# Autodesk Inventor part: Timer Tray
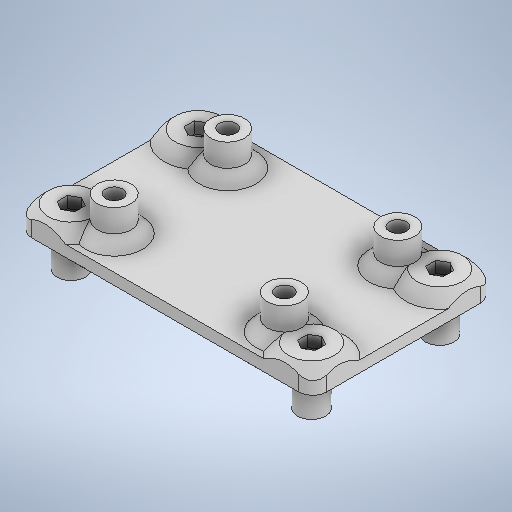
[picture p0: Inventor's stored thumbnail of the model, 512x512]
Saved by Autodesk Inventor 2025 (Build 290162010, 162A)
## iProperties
Created: 2023-12
Part Number: Timer Tray
Material: Generic
Document SubType Name: Modeling
Designer: Andrew
Density: 1 g/cm^3
Appearance: Default
Author: Andrew
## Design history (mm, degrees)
sketch "Sketch1"
  geometry: L1 (33.02, 20.32)-(-33.02, 20.32); L2 (-33.02, 20.32)-(-33.02, -20.32); L3 (-33.02, -20.32)-(33.02, -20.32); L4 (33.02, -20.32)-(33.02, 20.32); 1 further point
  constraints: 8 end point, 2 parallel, 1 horizontal, 1 perpendicular
  dimensions: "d0" = 40.64 distance of L3.end L1.start; "d1" = 66.04 distance between parallel lines of L2 L4; "d2" = 33.02 distance from line of L2 point (0, 0) (= 0.5 x d1); "d3" = 20.32 distance from line of L3 point (0, 0) (= 0.5 x d0)
extrude "Extrusion1" new body sketch "Sketch1" distance "d4" = 2.54; taper "d5" = 0 deg
fillet "Fillet1" dims "d6" = 3.175
sketch "Sketch2"
  geometry: L1 (33.02, 17.145)-(33.02, -17.145) reference; L2 (-33.02, -17.145)-(-33.02, 17.145) reference; L3 (29.845, -20.32)-(-29.845, -20.32) reference; L4 (-29.845, 20.32)-(29.845, 20.32) reference; C1 r 3.175 at (-27.051, 14.351); C2 r 1.397 at (-27.051, 14.351); C3 r 1.397 at (26.797, 14.351); C4 r 3.175 at (26.797, 14.351); C5 r 1.397 at (26.797, -14.351); C6 r 3.175 at (26.797, -14.351); C7 r 1.397 at (-27.305, -14.351); C8 r 3.175 at (-27.305, -14.351); 1 further point
  constraints: 8 centre point, 4 coincident, 2 horizontal alignment, 1 vertical alignment
  dimensions: "d7" = 2.794 diameter of C2; "d8" = 6.35 diameter of C1; "d9" = 2.794 diameter of C3 (= d7); "d10" = 6.35 diameter of C4 (= d8); "d11" = 2.794 diameter of C5 (= d7); "d12" = 6.35 diameter of C6 (= d8); "d13" = 2.794 diameter of C7 (= d7); "d14" = 6.35 diameter of C8 (= d8); "d18" = 66.04 distance between parallel lines of L1 L2 (derived); "d20" = 40.64 distance between parallel lines of L3 L4 (derived); "d42" = 56.642 dimension on C3 C2; "d43" = 31.496 dimension on C5 C3; "d44" = 28.702 distance of C5.centre C3.centre (derived); "d46" = 14.351 vertical distance of point (0, 0) C1.centre (= 0.5 x d44); "d47" = 27.051 horizontal distance of point (0, 0) C1.centre (= 0.5 x d48); "d48" = 54.102 distance of C6.centre C8.centre (derived); "d49" = 56.896 dimension on C5 C7
extrude "Extrusion2" join sketch "Sketch2" distance "d22" = 7.62; taper "d23" = 0 deg
sketch "Sketch3"
  geometry: L1 (33.02, -17.145)-(33.02, 17.145) reference; L2 (-33.02, 17.145)-(-33.02, -17.145) reference; L3 (29.845, 20.32)-(-29.845, 20.32) reference; L4 (-29.845, -20.32)-(29.845, -20.32) reference; C1 r 1.905 at (19.05, -12.7); C2 r 1.905 at (19.05, 12.7); C3 r 3.81 at (19.05, 12.7); C4 r 3.81 at (19.05, -12.7); C5 r 1.905 at (-19.05, -12.7); C6 r 3.81 at (-19.05, -12.7); C7 r 1.905 at (-19.05, 12.7); C8 r 3.81 at (-19.05, 12.7); 1 further point
  constraints: 8 centre point, 4 coincident, 2 horizontal alignment, 2 vertical alignment
  dimensions: "d24" = 3.81 diameter of C5; "d25" = 7.62 diameter of C6; "d26" = 3.81 diameter of C7 (= d24); "d27" = 7.62 diameter of C8 (= d25); "d28" = 3.81 diameter of C1 (= d24); "d29" = 7.62 diameter of C4 (= d25); "d30" = 3.81 diameter of C2 (= d26); "d31" = 7.62 diameter of C3 (= d27); "d32" = 38.1 distance of C7.centre C2.centre; "d33" = 25.4 distance of C2.centre C1.centre; "d34" = 13.97 distance from line of L1 C1.centre (= -0.5 x d32 + 0.5 x d35); "d35" = 66.04 distance between parallel lines of L2 L1 (derived); "d36" = 40.64 distance between parallel lines of L3 L4 (derived); "d37" = 7.62 distance from line of L4 C1.centre (= -0.5 x d33 + 0.5 x d36)
extrude "Extrusion3" join sketch "Sketch3" distance "d38" = 7.62; taper "d39" = 0 deg
sketch "Sketch4"
  geometry: C1 r 1.397 at (-27.051, 14.351) reference; C2 r 1.397 at (-27.305, -14.351) reference; C3 r 1.397 at (26.797, -14.351) reference; C4 r 1.397 at (26.797, 14.351) reference; C5 r 1.905 at (-19.05, 12.7) reference; C6 r 1.905 at (-19.05, -12.7) reference; C7 r 1.905 at (19.05, -12.7) reference; C8 r 1.905 at (19.05, 12.7) reference; 1 further point
extrude "Extrusion4" cut sketch "Sketch4" distance "d40" = 7.62; taper "d41" = 0 deg
sketch "Sketch5"
  geometry: L1 (-21.793, -11.116)-(-19.05, -9.532); L2 (-19.05, -9.532)-(-16.307, -11.116); L3 (-16.307, -11.116)-(-16.307, -14.284); L4 (-16.307, -14.284)-(-19.05, -15.868); L5 (-19.05, -15.868)-(-21.793, -14.284); L6 (-21.793, -14.284)-(-21.793, -11.116); L7 (-21.793, 14.284)-(-19.05, 15.868); L8 (-19.05, 15.868)-(-16.307, 14.284); L9 (-16.307, 14.284)-(-16.307, 11.116); L10 (-16.307, 11.116)-(-19.05, 9.532); L11 (-19.05, 9.532)-(-21.793, 11.116); L12 (-21.793, 11.116)-(-21.793, 14.284); L13 (16.307, -11.116)-(19.05, -9.532); L14 (19.05, -9.532)-(21.793, -11.116); L15 (21.793, -11.116)-(21.793, -14.284); L16 (21.793, -14.284)-(19.05, -15.868); L17 (19.05, -15.868)-(16.307, -14.284); L18 (16.307, -14.284)-(16.307, -11.116); L19 (16.307, 14.284)-(19.05, 15.868); L20 (19.05, 15.868)-(21.793, 14.284); L21 (21.793, 14.284)-(21.793, 11.116); L22 (21.793, 11.116)-(19.05, 9.532); L23 (19.05, 9.532)-(16.307, 11.116); L24 (16.307, 11.116)-(16.307, 14.284); C1 r 1.905 at (-19.05, -12.7) reference; C2 r 1.905 at (-19.05, 12.7) reference; C3 r 1.905 at (19.05, -12.7) reference; C4 r 1.905 at (19.05, 12.7) reference; C5 r 5.08 at (19.05, -12.7); C6 r 5.08 at (19.05, 12.7); C7 r 5.08 at (-19.05, 12.7); C8 r 5.08 at (-19.05, -12.7); 6 further points
  constraints: 48 end point, 8 coincident, 4 centre point, 4 vertical, 1 midpoint, 52 other
  dimensions: "d50" = 5.4864 distance between parallel lines of L20 L23 (= d52); "d51" = 5.4864 distance between parallel lines of L2 L5 (= d52); "d52" = 5.4864 distance between parallel lines of L10 L7; "d53" = 5.4864 distance between parallel lines of L16 L13 (= d52); "d54" = 10.16 diameter of C8; "d55" = 10.16 diameter of C7 (= d54); "d56" = 10.16 diameter of C5 (= d55); "d57" = 10.16 diameter of C6 (= d55)
extrude "Extrusion5" join sketch "Sketch5" distance "d58" = 2.54; taper "d59" = 0 deg
chamfer "Chamfer1" distance "d60" = 2.54; stored, may be unused: second distance "d61" = 3.175, angle "d62" = 45 deg
sketch "Sketch6"
  geometry: L1 (-27.305, 16.653)-(-25.311, 15.502); L2 (-25.311, 15.502)-(-25.311, 13.2); L3 (-25.311, 13.2)-(-27.305, 12.049); L4 (-27.305, 12.049)-(-29.299, 13.2); L5 (-29.299, 13.2)-(-29.299, 15.502); L6 (-29.299, 15.502)-(-27.305, 16.653); L7 (28.791, 15.502)-(28.791, 13.2); L8 (28.791, 13.2)-(26.797, 12.049); L9 (26.797, 12.049)-(24.803, 13.2); L10 (24.803, 13.2)-(24.803, 15.502); L11 (24.803, 15.502)-(26.797, 16.653); L12 (26.797, 16.653)-(28.791, 15.502); L13 (28.791, -13.2)-(28.791, -15.502); L14 (28.791, -15.502)-(26.797, -16.653); L15 (26.797, -16.653)-(24.803, -15.502); L16 (24.803, -15.502)-(24.803, -13.2); L17 (24.803, -13.2)-(26.797, -12.049); L18 (26.797, -12.049)-(28.791, -13.2); L19 (-29.045, -13.2)-(-27.051, -12.049); L20 (-27.051, -12.049)-(-25.057, -13.2); L21 (-25.057, -13.2)-(-25.057, -15.502); L22 (-25.057, -15.502)-(-27.051, -16.653); L23 (-27.051, -16.653)-(-29.045, -15.502); L24 (-29.045, -15.502)-(-29.045, -13.2); C1 r 5.08 at (26.797, 14.351); C2 r 5.08 at (26.797, -14.351); C3 r 5.08 at (-27.051, -14.351); C4 r 5.08 at (-27.305, 14.351); C5 r 1.397 at (-27.305, 14.351) reference; C6 r 1.397 at (26.797, 14.351) reference; C7 r 1.397 at (26.797, -14.351) reference; C8 r 1.397 at (-27.051, -14.351) reference; 9 further points
  constraints: 48 end point, 12 coincident, 4 centre point, 4 vertical, 52 other
  dimensions: "d63" = 3.9878 distance between parallel lines of L3 L6 (= d64); "d64" = 3.9878 distance between parallel lines of L9 L12; "d65" = 3.9878 distance between parallel lines of L14 L17 (= d64); "d66" = 3.9878 distance between parallel lines of L22 L19 (= d64); "d67" = 10.16 diameter of C4; "d68" = 10.16 diameter of C3; "d69" = 10.16 diameter of C2; "d70" = 10.16 diameter of C1
extrude "Extrusion6" join sketch "Sketch6" distance "d71" = 2.54; taper "d72" = 0 deg
chamfer "Chamfer2" distance "d73" = 2.54; stored, may be unused: second distance "d74" = 3.175, angle "d75" = 45 deg
chamfer "Chamfer3" distance "d76" = 2.54; stored, may be unused: second distance "d77" = 3.175, angle "d78" = 45 deg
body "Solid1"
node "Projected Loop1"
node "Projected Loop2"
node "Projected Loop3"
node "Projected Loop4"
node "Projected Loop5"
node "Projected Loop6"
node "Projected Loop7"
node "Projected Loop8"
